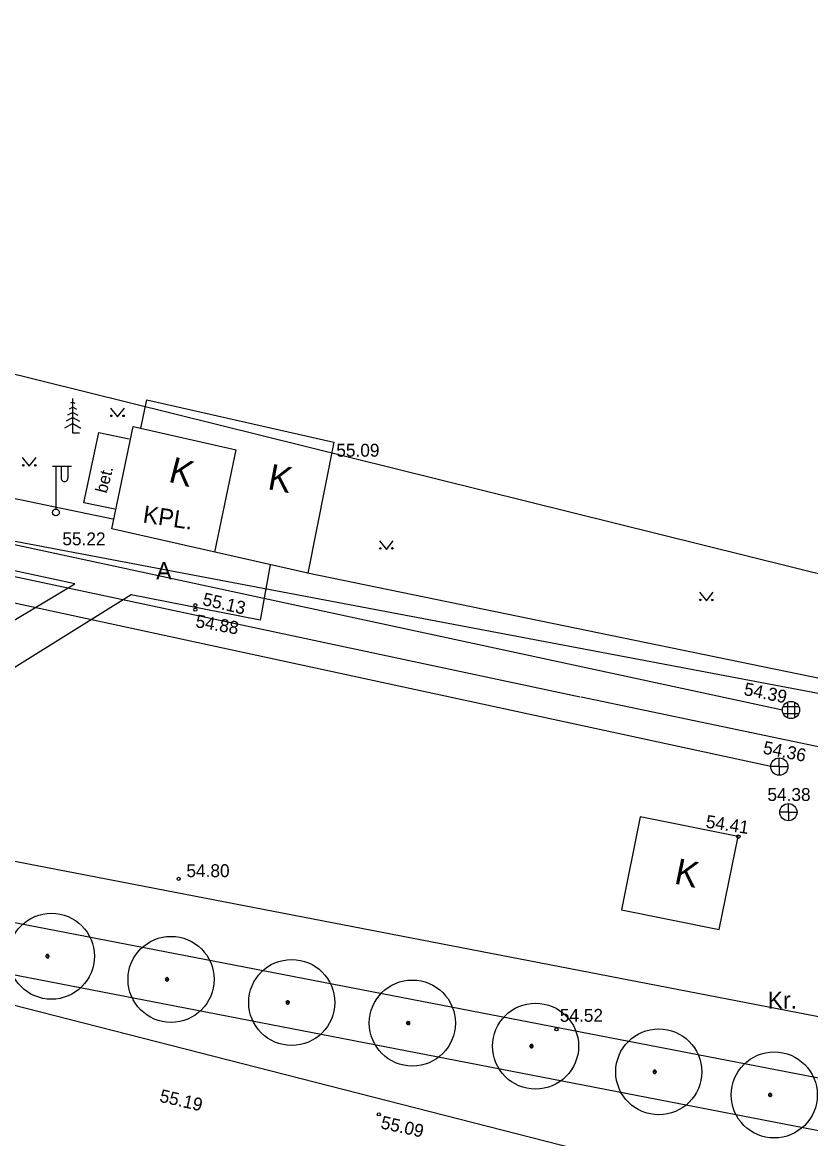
# Model space of a CAD drawing. Extents: x 9156 to 9809, y 2728 to 4000.
# Drawn here: x 9601.6 to 9647.5, y 3703.9 to 3768.8 of the extents above; entities that cross this region are included whole.
import ezdxf

# ---------------------------------------------------------------- set-up
doc = ezdxf.new("R2010")
doc.units = 0
for name, color, linetype in [('Level 1', 7, 'Continuous'), ('Level 17', 7, 'Continuous'), ('Level 18', 7, 'Continuous'), ('Level 54', 7, 'Continuous'), ('Level 56', 7, 'Continuous'), ('Level 7', 7, 'Continuous'), ('Level 9', 7, 'Continuous')]:
    doc.layers.add(name, color=color, linetype=linetype)

msp = doc.modelspace()

# ---------------------------------------------------------------- linework, layer by layer
at = {"layer": 'Level 1'}
msp.add_line((9518.632, 3768.823), (9760.318, 3708.94), dxfattribs=at)
msp.add_line((9518.632, 3768.823), (9760.318, 3708.94), dxfattribs=at)
at = {"layer": 'Level 17'}
for p, q in [((9654.208, 3709.808), (9594.947, 3721.262)), ((9653.543, 3706.371), (9594.283, 3717.825))]:
    msp.add_line(p, q, dxfattribs=at)
at = {"layer": 'Level 18'}
msp.add_line((9652.974, 3703.426), (9593.714, 3714.88), dxfattribs=at)
at = {"layer": 'Level 54'}
for p, q in [((9557.217, 3747.938), (9645.809, 3728.858)), ((9604.566, 3744.951), (9604.566, 3746.951)), ((9604.566, 3746.451), (9604.354, 3746.334)), ((9604.566, 3746.751), (9604.44, 3746.682)), ((9604.566, 3746.751), (9604.691, 3746.682)), ((9604.566, 3746.451), (9604.778, 3746.334)), ((9606.766, 3746.403), (9607.169, 3745.897)), ((9607.169, 3745.897), (9607.566, 3746.403)), ((9608.52, 3745.229), (9608.866, 3746.881)), ((9608.866, 3746.881), (9619.731, 3744.422)), ((9604.566, 3745.851), (9604.182, 3745.638)), ((9604.566, 3746.151), (9604.268, 3745.986)), ((9604.566, 3746.151), (9604.864, 3745.986)), ((9604.566, 3745.851), (9604.95, 3745.638)), ((9604.566, 3745.501), (9604.09, 3745.237)), ((9604.566, 3745.501), (9605.041, 3745.237)), ((9606.829, 3739.39), (9608.074, 3745.33)), ((9608.074, 3745.33), (9614.061, 3743.975)), ((9604.966, 3744.951), (9604.566, 3744.951)), ((9605.207, 3740.903), (9606.075, 3744.989)), ((9606.075, 3744.989), (9607.848, 3744.611)), ((9619.731, 3744.422), (9618.222, 3736.817)), ((9612.817, 3738.038), (9614.061, 3743.975)), ((9601.635, 3743.527), (9602.038, 3743.022)), ((9602.038, 3743.022), (9602.435, 3743.527)), ((9603.385, 3743.036), (9604.485, 3743.036)), ((9603.585, 3743.036), (9603.585, 3740.536)), ((9603.885, 3743.036), (9603.885, 3742.336)), ((9604.285, 3743.036), (9604.285, 3742.336)), ((9600.567, 3741.282), (9606.904, 3739.957)), ((9607.018, 3740.525), (9605.207, 3740.903)), ((9618.222, 3736.817), (9606.829, 3739.39)), ((9622.389, 3738.696), (9622.792, 3738.191)), ((9622.792, 3738.191), (9623.189, 3738.696)), ((9645.13, 3725.567), (9599.914, 3735.344)), ((9640.986, 3735.704), (9641.389, 3735.199)), ((9641.389, 3735.199), (9641.786, 3735.704)), ((9651.453, 3725.969), (9634.111, 3729.603)), ((9645.851, 3729.058), (9646.767, 3729.058)), ((9646.109, 3729.317), (9646.109, 3728.4)), ((9646.509, 3729.317), (9646.509, 3728.4)), ((9645.851, 3728.658), (9646.767, 3728.658)), ((9645.63, 3725.567), (9645.13, 3725.567)), ((9645.63, 3725.567), (9645.63, 3726.067)), ((9645.63, 3725.567), (9646.13, 3725.567)), ((9645.63, 3725.567), (9645.63, 3725.067)), ((9553.724, 3723.825), (9634.575, 3703.148)), ((9646.158, 3722.919), (9646.158, 3723.419)), ((9637.533, 3722.641), (9636.449, 3717.237)), ((9643.247, 3721.495), (9637.533, 3722.641)), ((9646.158, 3722.919), (9645.658, 3722.919)), ((9646.158, 3722.919), (9646.658, 3722.919)), ((9646.158, 3722.919), (9646.158, 3722.419))]:
    msp.add_line(p, q, dxfattribs=at)
for points in [[(9634.054, 3729.596), (9556.195, 3746.171), (9537.366, 3750)], [(9585.489, 3721.317), (9589.416, 3726.35), (9592.869, 3729.114), (9604.695, 3736.18), (9592.072, 3738.901), (9592.456, 3740.651), (9547.767, 3750)], [(9616.046, 3737.295), (9615.453, 3734.076), (9607.953, 3735.545), (9595.893, 3728.031), (9593.835, 3726.317), (9591.71, 3724.468), (9590.454, 3722.439), (9589.512, 3720.095), (9588.869, 3717.613)], [(9673.173, 3725.267), (9669.213, 3726.254), (9659.652, 3728.282), (9618.218, 3736.801)], [(9636.449, 3717.237), (9642.139, 3716.096), (9643.247, 3721.495)]]:
    msp.add_lwpolyline(points, dxfattribs=at)
for centre, radius in [((9606.816, 3745.953), 0.0428), ((9607.516, 3745.953), 0.0452), ((9601.685, 3743.077), 0.0428), ((9602.385, 3743.077), 0.0452), ((9603.585, 3740.336), 0.2), ((9622.439, 3738.246), 0.0428), ((9623.139, 3738.246), 0.0452), ((9641.036, 3735.254), 0.0428), ((9641.736, 3735.254), 0.0452), ((9611.689, 3734.946), 0.0909), ((9611.689, 3734.686), 0.0909), ((9646.309, 3728.858), 0.5), ((9645.63, 3725.567), 0.5), ((9646.158, 3722.919), 0.5), ((9643.247, 3721.495), 0.102), ((9610.719, 3719.046), 0.0909), ((9632.678, 3710.291), 0.0909), ((9622.353, 3705.353), 0.0909)]:
    msp.add_circle(centre, radius, dxfattribs=at)
msp.add_arc((9604.085, 3742.336), 0.2, 179.93931, 0.0607, dxfattribs=at)
at = {"layer": 'Level 56'}
for p, q in [((9654.208, 3709.808), (9594.947, 3721.262)), ((9653.543, 3706.371), (9594.283, 3717.825)), ((9652.974, 3703.426), (9593.714, 3714.88))]:
    msp.add_line(p, q, dxfattribs=at)
at = {"layer": 'Level 7'}
for p, q in [((9560.67, 3746.36), (9614.195, 3736.215)), ((9614.195, 3736.215), (9667.72, 3726.07))]:
    msp.add_line(p, q, dxfattribs=at)
at = {"layer": 'Level 9'}
for p, q in [((9603.015, 3714.557), (9602.993, 3714.559)), ((9602.993, 3714.531), (9603.015, 3714.534)), ((9603.001, 3714.587), (9603.022, 3714.579)), ((9603.021, 3714.512), (9603.002, 3714.503)), ((9603.034, 3714.597), (9603.017, 3714.611)), ((9603.038, 3714.629), (9603.05, 3714.611)), ((9603.071, 3714.621), (9603.065, 3714.641)), ((9603.103, 3714.544), (9603.082, 3714.544)), ((9603.093, 3714.646), (9603.093, 3714.624)), ((9603.093, 3714.533), (9603.093, 3714.554)), ((9603.114, 3714.621), (9603.12, 3714.642)), ((9603.147, 3714.63), (9603.136, 3714.611)), ((9603.152, 3714.597), (9603.169, 3714.611)), ((9603.184, 3714.587), (9603.165, 3714.577)), ((9603.165, 3714.513), (9603.185, 3714.504)), ((9603.171, 3714.556), (9603.192, 3714.56)), ((9603.193, 3714.531), (9603.171, 3714.535)), ((9603.017, 3714.479), (9603.033, 3714.494)), ((9603.05, 3714.478), (9603.038, 3714.46)), ((9603.064, 3714.449), (9603.07, 3714.469)), ((9603.093, 3714.466), (9603.092, 3714.444)), ((9603.121, 3714.448), (9603.115, 3714.469)), ((9603.135, 3714.478), (9603.147, 3714.46)), ((9603.17, 3714.48), (9603.153, 3714.494)), ((9609.966, 3713.213), (9609.945, 3713.216)), ((9609.953, 3713.243), (9609.973, 3713.235)), ((9609.985, 3713.253), (9609.968, 3713.267)), ((9609.99, 3713.286), (9610.001, 3713.267)), ((9610.023, 3713.277), (9610.016, 3713.298)), ((9610.055, 3713.2), (9610.034, 3713.2)), ((9610.044, 3713.302), (9610.044, 3713.28)), ((9610.044, 3713.19), (9610.044, 3713.211)), ((9610.066, 3713.277), (9610.072, 3713.298)), ((9610.098, 3713.286), (9610.088, 3713.267)), ((9610.104, 3713.253), (9610.12, 3713.267)), ((9610.136, 3713.243), (9610.116, 3713.233)), ((9610.122, 3713.212), (9610.144, 3713.216)), ((9609.945, 3713.187), (9609.966, 3713.191)), ((9609.973, 3713.169), (9609.953, 3713.159)), ((9609.968, 3713.136), (9609.984, 3713.15)), ((9610.002, 3713.135), (9609.99, 3713.117)), ((9610.015, 3713.105), (9610.021, 3713.126)), ((9610.044, 3713.122), (9610.044, 3713.101)), ((9610.072, 3713.105), (9610.067, 3713.126)), ((9610.086, 3713.135), (9610.099, 3713.116)), ((9610.121, 3713.136), (9610.105, 3713.151)), ((9610.116, 3713.169), (9610.136, 3713.161)), ((9610.144, 3713.188), (9610.123, 3713.191)), ((9616.964, 3711.9), (9616.984, 3711.892)), ((9616.996, 3711.91), (9616.98, 3711.924)), ((9617.001, 3711.942), (9617.013, 3711.924)), ((9617.034, 3711.934), (9617.027, 3711.954)), ((9617.056, 3711.958), (9617.056, 3711.937)), ((9617.077, 3711.934), (9617.083, 3711.955)), ((9617.11, 3711.943), (9617.099, 3711.924)), ((9617.115, 3711.91), (9617.132, 3711.924)), ((9616.978, 3711.869), (9616.956, 3711.872)), ((9616.956, 3711.844), (9616.978, 3711.847)), ((9616.984, 3711.825), (9616.964, 3711.815)), ((9616.979, 3711.792), (9616.996, 3711.807)), ((9617.013, 3711.791), (9617.001, 3711.773)), ((9617.027, 3711.761), (9617.033, 3711.782)), ((9617.066, 3711.857), (9617.045, 3711.857)), ((9617.056, 3711.779), (9617.055, 3711.757)), ((9617.056, 3711.846), (9617.056, 3711.867)), ((9617.083, 3711.761), (9617.078, 3711.782)), ((9617.098, 3711.791), (9617.11, 3711.773)), ((9617.132, 3711.793), (9617.116, 3711.807)), ((9617.147, 3711.899), (9617.128, 3711.89)), ((9617.128, 3711.826), (9617.148, 3711.817)), ((9617.134, 3711.869), (9617.155, 3711.873)), ((9617.155, 3711.844), (9617.134, 3711.848)), ((9623.989, 3710.675), (9623.967, 3710.678)), ((9623.967, 3710.649), (9623.989, 3710.653)), ((9623.975, 3710.705), (9623.996, 3710.697)), ((9623.995, 3710.631), (9623.976, 3710.621)), ((9624.008, 3710.715), (9623.991, 3710.729)), ((9623.991, 3710.598), (9624.007, 3710.612)), ((9624.012, 3710.748), (9624.024, 3710.729)), ((9624.045, 3710.739), (9624.039, 3710.76)), ((9624.077, 3710.662), (9624.056, 3710.662)), ((9624.067, 3710.764), (9624.067, 3710.742)), ((9624.067, 3710.652), (9624.067, 3710.673)), ((9624.088, 3710.739), (9624.094, 3710.76)), ((9624.121, 3710.748), (9624.11, 3710.729)), ((9624.126, 3710.715), (9624.143, 3710.729)), ((9624.144, 3710.598), (9624.127, 3710.613)), ((9624.158, 3710.705), (9624.139, 3710.695)), ((9624.139, 3710.631), (9624.159, 3710.623)), ((9624.145, 3710.674), (9624.166, 3710.678)), ((9624.167, 3710.65), (9624.145, 3710.653)), ((9624.024, 3710.597), (9624.012, 3710.579)), ((9624.038, 3710.567), (9624.044, 3710.588)), ((9624.067, 3710.585), (9624.066, 3710.563)), ((9624.095, 3710.567), (9624.089, 3710.588)), ((9624.109, 3710.597), (9624.121, 3710.579)), ((9631.149, 3709.331), (9631.128, 3709.334)), ((9631.128, 3709.306), (9631.149, 3709.309)), ((9631.136, 3709.362), (9631.156, 3709.354)), ((9631.168, 3709.372), (9631.151, 3709.386)), ((9631.173, 3709.404), (9631.184, 3709.386)), ((9631.206, 3709.396), (9631.199, 3709.416)), ((9631.238, 3709.319), (9631.217, 3709.319)), ((9631.227, 3709.42), (9631.227, 3709.399)), ((9631.227, 3709.308), (9631.227, 3709.329)), ((9631.249, 3709.396), (9631.255, 3709.417)), ((9631.281, 3709.405), (9631.271, 3709.386)), ((9631.287, 3709.372), (9631.303, 3709.386)), ((9631.319, 3709.362), (9631.299, 3709.352)), ((9631.305, 3709.331), (9631.327, 3709.335)), ((9631.327, 3709.306), (9631.306, 3709.31)), ((9631.156, 3709.287), (9631.136, 3709.277)), ((9631.151, 3709.254), (9631.167, 3709.269)), ((9631.185, 3709.253), (9631.173, 3709.235)), ((9631.198, 3709.223), (9631.204, 3709.244)), ((9631.227, 3709.241), (9631.227, 3709.219)), ((9631.255, 3709.223), (9631.25, 3709.244)), ((9631.269, 3709.253), (9631.281, 3709.235)), ((9631.304, 3709.255), (9631.288, 3709.269)), ((9631.299, 3709.288), (9631.319, 3709.279)), ((9638.31, 3707.838), (9638.288, 3707.841)), ((9638.288, 3707.813), (9638.31, 3707.816)), ((9638.296, 3707.869), (9638.317, 3707.861)), ((9638.316, 3707.794), (9638.296, 3707.785)), ((9638.311, 3707.761), (9638.328, 3707.776)), ((9638.329, 3707.879), (9638.312, 3707.893)), ((9638.333, 3707.911), (9638.345, 3707.893)), ((9638.345, 3707.76), (9638.333, 3707.742)), ((9638.366, 3707.903), (9638.359, 3707.923)), ((9638.359, 3707.731), (9638.365, 3707.751)), ((9638.398, 3707.826), (9638.377, 3707.826)), ((9638.388, 3707.748), (9638.387, 3707.726)), ((9638.388, 3707.927), (9638.388, 3707.906)), ((9638.388, 3707.815), (9638.388, 3707.836)), ((9638.409, 3707.903), (9638.415, 3707.924)), ((9638.415, 3707.73), (9638.41, 3707.751)), ((9638.43, 3707.76), (9638.442, 3707.742)), ((9638.442, 3707.912), (9638.431, 3707.893)), ((9638.447, 3707.879), (9638.464, 3707.893)), ((9638.465, 3707.762), (9638.448, 3707.776)), ((9638.479, 3707.869), (9638.46, 3707.859)), ((9638.46, 3707.795), (9638.48, 3707.786)), ((9638.466, 3707.838), (9638.487, 3707.842)), ((9638.487, 3707.813), (9638.466, 3707.817)), ((9645.023, 3706.495), (9645.001, 3706.498)), ((9645.001, 3706.469), (9645.023, 3706.473)), ((9645.009, 3706.525), (9645.029, 3706.517)), ((9645.029, 3706.451), (9645.009, 3706.441)), ((9645.024, 3706.418), (9645.041, 3706.432)), ((9645.041, 3706.535), (9645.025, 3706.549)), ((9645.046, 3706.568), (9645.058, 3706.549)), ((9645.058, 3706.417), (9645.046, 3706.399)), ((9645.079, 3706.559), (9645.072, 3706.58)), ((9645.072, 3706.387), (9645.078, 3706.408)), ((9645.111, 3706.482), (9645.09, 3706.482)), ((9645.101, 3706.404), (9645.1, 3706.383)), ((9645.101, 3706.584), (9645.101, 3706.562)), ((9645.101, 3706.472), (9645.101, 3706.493)), ((9645.122, 3706.559), (9645.128, 3706.58)), ((9645.128, 3706.387), (9645.123, 3706.408)), ((9645.143, 3706.417), (9645.155, 3706.398)), ((9645.155, 3706.568), (9645.144, 3706.549)), ((9645.16, 3706.535), (9645.177, 3706.549)), ((9645.177, 3706.418), (9645.161, 3706.433)), ((9645.192, 3706.525), (9645.173, 3706.515)), ((9645.173, 3706.451), (9645.193, 3706.442)), ((9645.179, 3706.494), (9645.2, 3706.498)), ((9645.2, 3706.47), (9645.179, 3706.473))]:
    msp.add_line(p, q, dxfattribs=at)
for centre in [(9603.328, 3714.544), (9610.279, 3713.2), (9617.291, 3711.857), (9624.302, 3710.662), (9631.462, 3709.319), (9638.623, 3707.826), (9645.336, 3706.482)]:
    msp.add_circle(centre, 2.5, dxfattribs=at)
for centre, radius, start, end in [((9603.093, 3714.545), 0.101, 155.31226, 171.70421), ((9603.093, 3714.545), 0.101, 187.96706, 204.86254), ((9603.093, 3714.545), 0.0788, 171.54306, 187.6203), ((9603.093, 3714.545), 0.101, 122.84338, 139.02216), ((9603.093, 3714.545), 0.0788, 204.45291, 220.47744), ((9603.093, 3714.545), 0.0788, 138.64322, 154.57953), ((9603.093, 3714.545), 0.0788, 105.95586, 123.05638), ((9603.093, 3714.545), 0.101, 90.03559, 106.34199), ((9603.093, 3714.545), 0.0788, 74.31, 90.04303), ((9603.093, 3714.545), 0.101, 57.61079, 74.19806), ((9603.093, 3714.545), 0.0788, 41.20616, 56.77954), ((9603.093, 3714.545), 0.0788, 8.06191, 24.03317), ((9603.093, 3714.545), 0.0788, 336.05568, 352.75584), ((9603.093, 3714.545), 0.101, 24.53942, 40.98516), ((9603.093, 3714.545), 0.101, 319.77774, 336.07384), ((9603.093, 3714.545), 0.101, 352.27003, 8.58296), ((9603.093, 3714.545), 0.101, 220.71222, 237.11658), ((9603.093, 3714.545), 0.0788, 237.451, 253.08433), ((9603.093, 3714.545), 0.101, 253.29517, 269.57177), ((9603.093, 3714.545), 0.0788, 269.94612, 286.34731), ((9603.093, 3714.545), 0.101, 285.97198, 302.5562), ((9603.093, 3714.545), 0.0788, 302.25403, 320.08604), ((9610.044, 3713.201), 0.101, 155.31226, 171.70421), ((9610.044, 3713.201), 0.0788, 171.54306, 187.6203), ((9610.044, 3713.201), 0.101, 122.84338, 139.02216), ((9610.044, 3713.201), 0.0788, 138.64322, 154.57953), ((9610.044, 3713.201), 0.0788, 105.95586, 123.05638), ((9610.044, 3713.201), 0.101, 90.03559, 106.34199), ((9610.044, 3713.201), 0.0788, 74.31, 90.04303), ((9610.044, 3713.201), 0.101, 57.61079, 74.19806), ((9610.044, 3713.201), 0.0788, 41.20616, 56.77954), ((9610.044, 3713.201), 0.0788, 8.06191, 24.03317), ((9610.044, 3713.201), 0.101, 24.53942, 40.98516), ((9610.044, 3713.201), 0.101, 352.27003, 8.58296), ((9610.044, 3713.201), 0.101, 187.96706, 204.86254), ((9610.044, 3713.201), 0.101, 220.71222, 237.11658), ((9610.044, 3713.201), 0.0788, 204.45291, 220.47744), ((9610.044, 3713.201), 0.0788, 237.451, 253.08433), ((9610.044, 3713.201), 0.101, 253.29517, 269.57177), ((9610.044, 3713.201), 0.0788, 269.94612, 286.34731), ((9610.044, 3713.201), 0.101, 285.97198, 302.5562), ((9610.044, 3713.201), 0.0788, 302.25403, 320.08604), ((9610.044, 3713.201), 0.0788, 336.05568, 352.75584), ((9610.044, 3713.201), 0.101, 319.77774, 336.07384), ((9617.056, 3711.858), 0.101, 155.31226, 171.70421), ((9617.056, 3711.858), 0.101, 122.84338, 139.02216), ((9617.056, 3711.858), 0.0788, 138.64322, 154.57953), ((9617.056, 3711.858), 0.0788, 105.95586, 123.05638), ((9617.056, 3711.858), 0.101, 90.03559, 106.34199), ((9617.056, 3711.858), 0.0788, 74.31, 90.04303), ((9617.056, 3711.858), 0.101, 57.61079, 74.19806), ((9617.056, 3711.858), 0.0788, 41.20616, 56.77954), ((9617.056, 3711.858), 0.101, 24.53942, 40.98516), ((9617.056, 3711.858), 0.101, 187.96706, 204.86254), ((9617.056, 3711.858), 0.0788, 171.54306, 187.6203), ((9617.056, 3711.858), 0.101, 220.71222, 237.11658), ((9617.056, 3711.858), 0.0788, 204.45291, 220.47744), ((9617.056, 3711.858), 0.0788, 237.451, 253.08433), ((9617.056, 3711.858), 0.101, 253.29517, 269.57177), ((9617.056, 3711.858), 0.0788, 269.94612, 286.34731), ((9617.056, 3711.858), 0.101, 285.97198, 302.5562), ((9617.056, 3711.858), 0.0788, 302.25403, 320.08604), ((9617.056, 3711.858), 0.0788, 8.06191, 24.03317), ((9617.056, 3711.858), 0.0788, 336.05568, 352.75584), ((9617.056, 3711.858), 0.101, 319.77774, 336.07384), ((9617.056, 3711.858), 0.101, 352.27003, 8.58296), ((9624.067, 3710.663), 0.101, 155.31226, 171.70421), ((9624.067, 3710.663), 0.101, 187.96706, 204.86254), ((9624.067, 3710.663), 0.0788, 171.54306, 187.6203), ((9624.067, 3710.663), 0.101, 122.84338, 139.02216), ((9624.067, 3710.663), 0.0788, 204.45291, 220.47744), ((9624.067, 3710.663), 0.0788, 138.64322, 154.57953), ((9624.067, 3710.663), 0.0788, 105.95586, 123.05638), ((9624.067, 3710.663), 0.101, 90.03559, 106.34199), ((9624.067, 3710.663), 0.0788, 74.31, 90.04303), ((9624.067, 3710.663), 0.101, 57.61079, 74.19806), ((9624.067, 3710.663), 0.0788, 302.25403, 320.08604), ((9624.067, 3710.663), 0.0788, 41.20616, 56.77954), ((9624.067, 3710.663), 0.0788, 8.06191, 24.03317), ((9624.067, 3710.663), 0.0788, 336.05568, 352.75584), ((9624.067, 3710.663), 0.101, 24.53942, 40.98516), ((9624.067, 3710.663), 0.101, 319.77774, 336.07384), ((9624.067, 3710.663), 0.101, 352.27003, 8.58296), ((9624.067, 3710.663), 0.101, 220.71222, 237.11658), ((9624.067, 3710.663), 0.0788, 237.451, 253.08433), ((9624.067, 3710.663), 0.101, 253.29517, 269.57177), ((9624.067, 3710.663), 0.0788, 269.94612, 286.34731), ((9624.067, 3710.663), 0.101, 285.97198, 302.5562), ((9631.227, 3709.32), 0.101, 155.31226, 171.70421), ((9631.227, 3709.32), 0.101, 187.96706, 204.86254), ((9631.227, 3709.32), 0.0788, 171.54306, 187.6203), ((9631.227, 3709.32), 0.101, 122.84338, 139.02216), ((9631.227, 3709.32), 0.0788, 138.64322, 154.57953), ((9631.227, 3709.32), 0.0788, 105.95586, 123.05638), ((9631.227, 3709.32), 0.101, 90.03559, 106.34199), ((9631.227, 3709.32), 0.0788, 74.31, 90.04303), ((9631.227, 3709.32), 0.101, 57.61079, 74.19806), ((9631.227, 3709.32), 0.0788, 41.20616, 56.77954), ((9631.227, 3709.32), 0.0788, 8.06191, 24.03317), ((9631.227, 3709.32), 0.0788, 336.05568, 352.75584), ((9631.227, 3709.32), 0.101, 24.53942, 40.98516), ((9631.227, 3709.32), 0.101, 352.27003, 8.58296), ((9631.227, 3709.32), 0.101, 220.71222, 237.11658), ((9631.227, 3709.32), 0.0788, 204.45291, 220.47744), ((9631.227, 3709.32), 0.0788, 237.451, 253.08433), ((9631.227, 3709.32), 0.101, 253.29517, 269.57177), ((9631.227, 3709.32), 0.0788, 269.94612, 286.34731), ((9631.227, 3709.32), 0.101, 285.97198, 302.5562), ((9631.227, 3709.32), 0.0788, 302.25403, 320.08604), ((9631.227, 3709.32), 0.101, 319.77774, 336.07384), ((9638.388, 3707.827), 0.101, 155.31226, 171.70421), ((9638.388, 3707.827), 0.101, 187.96706, 204.86254), ((9638.388, 3707.827), 0.0788, 171.54306, 187.6203), ((9638.388, 3707.827), 0.101, 220.71222, 237.11658), ((9638.388, 3707.827), 0.101, 122.84338, 139.02216), ((9638.388, 3707.827), 0.0788, 204.45291, 220.47744), ((9638.388, 3707.827), 0.0788, 138.64322, 154.57953), ((9638.388, 3707.827), 0.0788, 105.95586, 123.05638), ((9638.388, 3707.827), 0.0788, 237.451, 253.08433), ((9638.388, 3707.827), 0.101, 90.03559, 106.34199), ((9638.388, 3707.827), 0.101, 253.29517, 269.57177), ((9638.388, 3707.827), 0.0788, 74.31, 90.04303), ((9638.388, 3707.827), 0.0788, 269.94612, 286.34731), ((9638.388, 3707.827), 0.101, 57.61079, 74.19806), ((9638.388, 3707.827), 0.101, 285.97198, 302.5562), ((9638.388, 3707.827), 0.0788, 302.25403, 320.08604), ((9638.388, 3707.827), 0.0788, 41.20616, 56.77954), ((9638.388, 3707.827), 0.0788, 8.06191, 24.03317), ((9638.388, 3707.827), 0.0788, 336.05568, 352.75584), ((9638.388, 3707.827), 0.101, 24.53942, 40.98516), ((9638.388, 3707.827), 0.101, 319.77774, 336.07384), ((9638.388, 3707.827), 0.101, 352.27003, 8.58296), ((9645.101, 3706.483), 0.101, 155.31226, 171.70421), ((9645.101, 3706.483), 0.101, 187.96706, 204.86254), ((9645.101, 3706.483), 0.0788, 171.54306, 187.6203), ((9645.101, 3706.483), 0.101, 220.71222, 237.11658), ((9645.101, 3706.483), 0.101, 122.84338, 139.02216), ((9645.101, 3706.483), 0.0788, 138.64322, 154.57953), ((9645.101, 3706.483), 0.0788, 204.45291, 220.47744), ((9645.101, 3706.483), 0.0788, 105.95586, 123.05638), ((9645.101, 3706.483), 0.0788, 237.451, 253.08433), ((9645.101, 3706.483), 0.101, 90.03559, 106.34199), ((9645.101, 3706.483), 0.101, 253.29517, 269.57177), ((9645.101, 3706.483), 0.0788, 74.31, 90.04303), ((9645.101, 3706.483), 0.0788, 269.94612, 286.34731), ((9645.101, 3706.483), 0.101, 57.61079, 74.19806), ((9645.101, 3706.483), 0.101, 285.97198, 302.5562), ((9645.101, 3706.483), 0.0788, 302.25403, 320.08604), ((9645.101, 3706.483), 0.0788, 41.20616, 56.77954), ((9645.101, 3706.483), 0.0788, 8.06191, 24.03317), ((9645.101, 3706.483), 0.0788, 336.05568, 352.75584), ((9645.101, 3706.483), 0.101, 24.53942, 40.98516), ((9645.101, 3706.483), 0.101, 319.77774, 336.07384), ((9645.101, 3706.483), 0.101, 352.27003, 8.58296)]:
    msp.add_arc(centre, radius, start, end, dxfattribs=at)

# ---------------------------------------------------------------- texts
at = {"layer": 'Level 54'}
for s, height, p in [('55.09', 0.75, (9619.882, 3743.578)), ('55.22', 0.75, (9603.962, 3738.43)), ('A', 1, (9609.418, 3736.457)), ('54.38', 0.75, (9644.938, 3723.569)), ('54.80', 0.75, (9611.171, 3719.141)), ('Kr.', 1, (9644.95, 3711.494)), ('54.52', 0.75, (9632.873, 3710.734))]:
    msp.add_text(s, height=height, dxfattribs=at).set_placement(p)
for s, height, rotation, p in [('K', 1.5, 345.57135, (9610.07, 3742.138)), ('K', 1.5, 349.41833, (9615.838, 3741.702)), ('bet.', 0.7, 75.77569, (9606.54, 3741.414)), ('KPL.', 1, 351.45846, (9608.599, 3739.761)), ('55.13', 0.75, 347.00608, (9612.063, 3734.962)), ('54.88', 0.75, 350.02111, (9611.662, 3733.676)), ('54.39', 0.75, 348.6629, (9643.526, 3729.732)), ('54.36', 0.75, 348.66306, (9644.64, 3726.332)), ('54.41', 0.75, 351.39712, (9641.321, 3722.022)), ('K', 1.5, 348.28253, (9639.461, 3718.781)), ('55.19', 0.75, 346.80806, (9609.564, 3706.098)), ('55.09', 0.75, 347.24003, (9622.416, 3704.55))]:
    msp.add_text(s, height=height, rotation=rotation, dxfattribs=at).set_placement(p)

doc.saveas('drawing.dxf')
